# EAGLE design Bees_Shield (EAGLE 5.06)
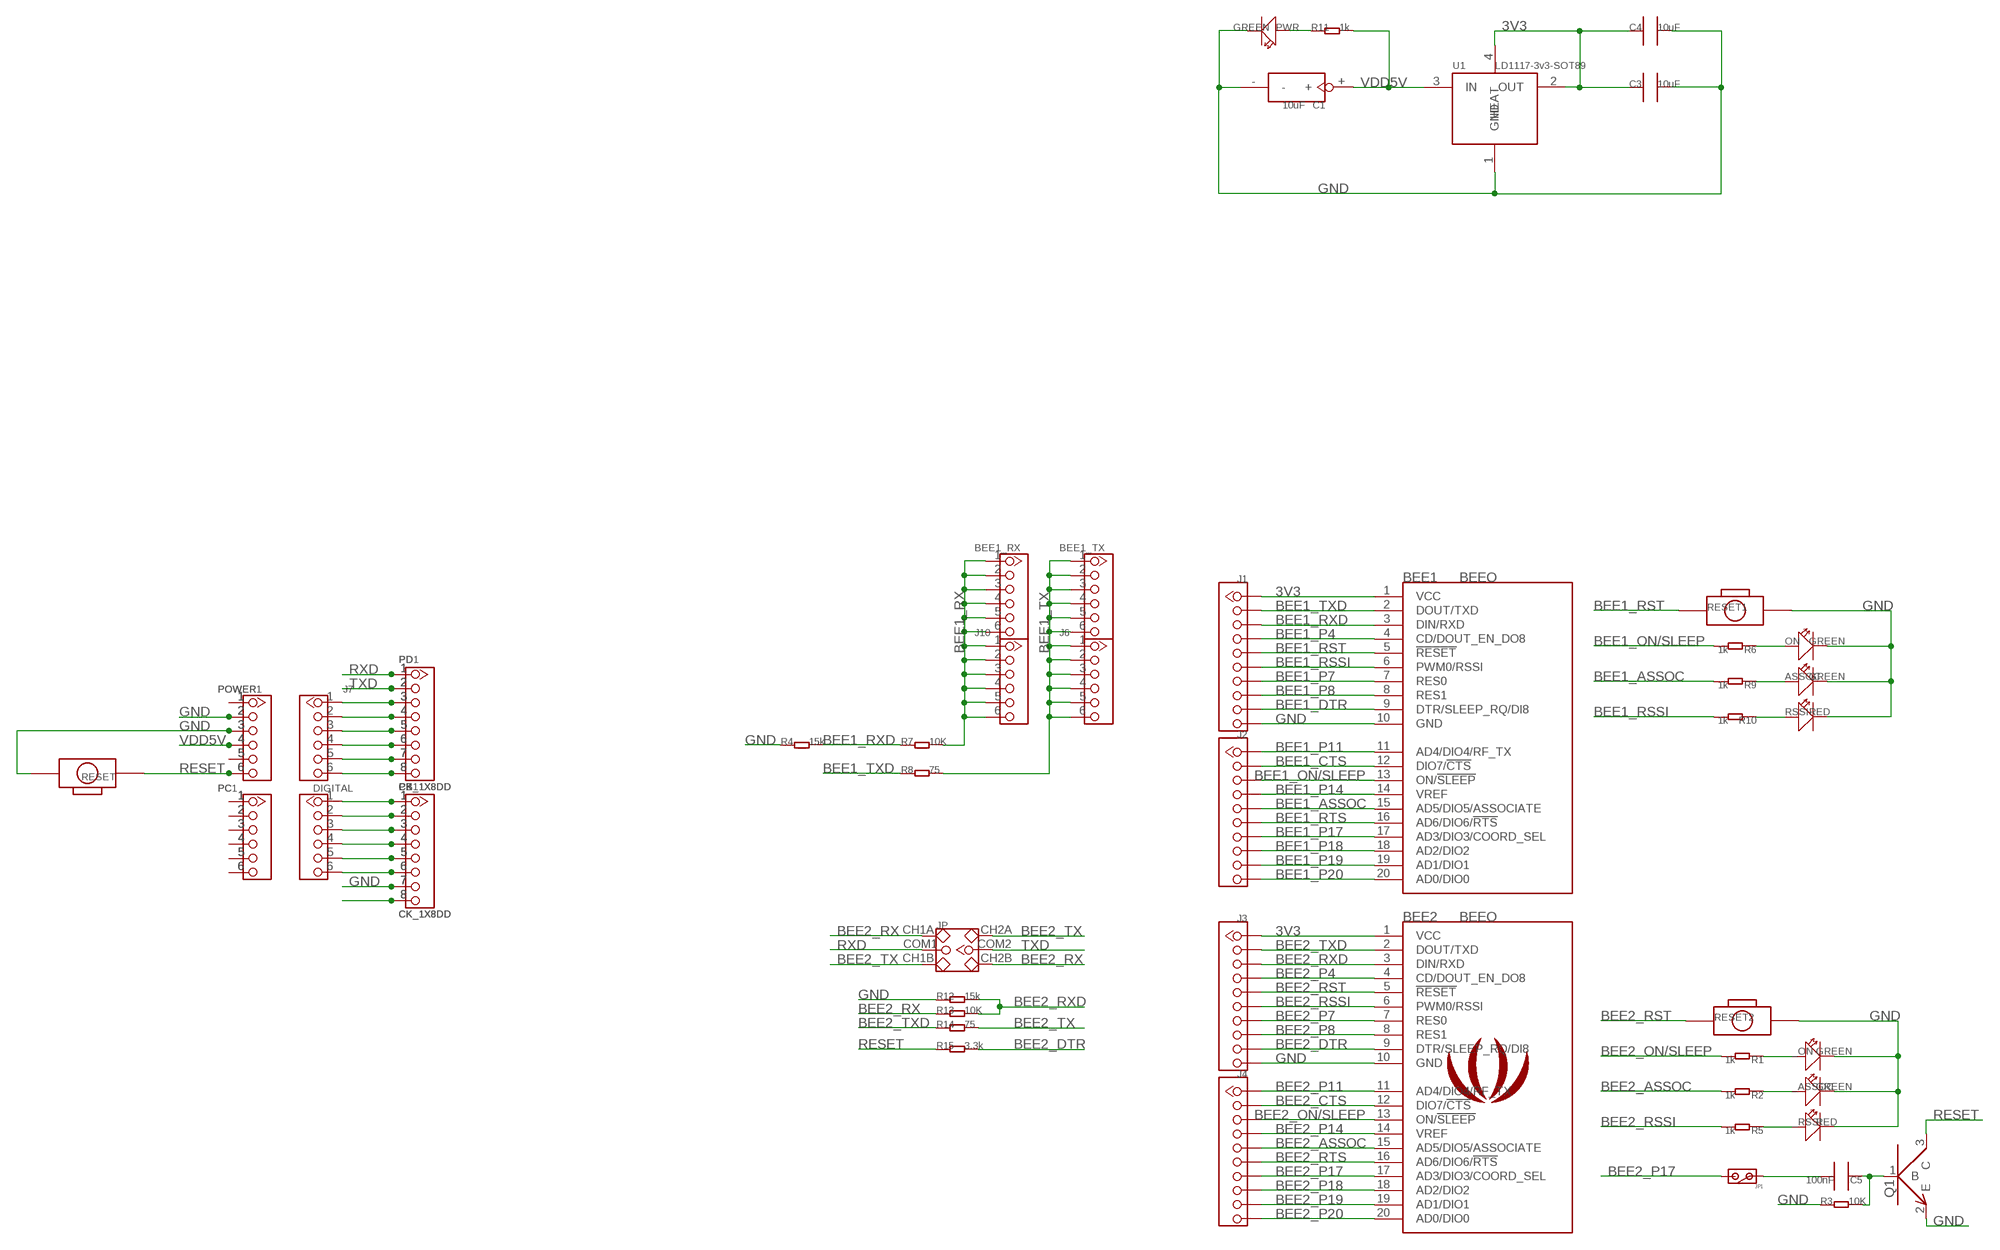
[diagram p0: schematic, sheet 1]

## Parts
_ASSOC  GREEN  LED0603_DD  [LED0603]
_ON  GREEN  LED0603_DD  [LED0603]
_RSSI  RED  LED0603_DD  [LED0603]
ASSOC  GREEN  LED0603_DD  [LED0603]
BEE1  BEEO  [BEE]
BEE1_RX  HEADER_1X6  [CK_1X6]
BEE1_TX  HEADER_1X6  [CK_1X6]
BEE2  BEEO  [BEE]
C1  10uF  C_TAN_B  [C_TAN_3X3.5]
C3  10uF  C0805  [0805]
C4  10uF  C0805  [0805]
C5  100nF  C0603  [0603]
DIGITAL  HEADER_1X6  [CK_1X6]
J1  CK1X10DD  [CK1X10]
J2  CK1X10DD  [CK1X10]
J3  CK1X10DD  [CK1X10]
J4  CK1X10DD  [CK1X10]
J6  HEADER_1X6  [CK_1X6]
J7  HEADER_1X6  [CK_1X6]
J10  HEADER_1X6  [CK_1X6]
JP  2.54SW_2CH_SMD  [7X7_SMD_2CH]
JP1  JP_SW  [JP_SW]
ON  GREEN  LED0603_DD  [LED0603]
PB  CK_1X8DD  [CK_1X8]
PB1  CK_1X8DD  [CK_1X8]
PC  HEADER_1X6  [CK_1X6]
PC1  HEADER_1X6  [CK_1X6]
PD  CK_1X8DD  [CK_1X8]
PD1  CK_1X8DD  [CK_1X8]
POWER  HEADER_1X6  [CK_1X6]
POWER1  HEADER_1X6  [CK_1X6]
PWR  GREEN  LED0603_DD  [LED0603]
Q1  NPN_9013  [SOT23]
R1  1k  R0603  [0603]
R2  1k  R0603  [0603]
R3  10K  R0603  [0603]
R4  15k  R0603  [0603]
R5  1k  R0603  [0603]
R6  1k  R0603  [0603]
R7  10K  R0603  [0603]
R8  75  R0603  [0603]
R9  1k  R0603  [0603]
R10  1k  R0603  [0603]
R11  1k  R0603  [0603]
R12  15k  R0603  [0603]
R13  10K  R0603  [0603]
R14  75  R0603  [0603]
R15  3.3k  R0603  [0603]
RESET  BOTTON_1  BOTTON_1_DP  [BTN_5.0_RST]
RESET1  BOTTON_1  BOTTON_1_DP  [BTN_5.0_RST]
RESET2  BOTTON_1  BOTTON_1_DP  [BTN_5.0_RST]
RSSI  RED  LED0603_DD  [LED0603]
U1  LD1117-3v3-SOT89  LD1117SOT89  [SOT89]
U$1  SEEEDSTUDIO  [SEEED_MASK]

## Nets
3V3: BEE1.1(VCC) BEE2.1(VCC) C3.1 C4.1 J1.1 J3.1 U1.2(OUT) U1.4(HEAT)
BEE1_ASSOC: BEE1.15(AD5/DIO5/ASSOCIATE) J2.5 R9.2
BEE1_CTS: BEE1.12(DIO7/!CTS) J2.2
BEE1_DTR: BEE1.9(DTR/SLEEP_RQ/DI8) J1.9
BEE1_ON/SLEEP: BEE1.13(ON/!SLEEP) J2.3 R6.2
BEE1_P4: BEE1.4(CD/DOUT_EN_DO8) J1.4
BEE1_P7: BEE1.7(RES0) J1.7
BEE1_P8: BEE1.8(RES1) J1.8
BEE1_P11: BEE1.11(AD4/DIO4/RF_TX) J2.1
BEE1_P14: BEE1.14(VREF) J2.4
BEE1_P17: BEE1.17(AD3/DIO3/COORD_SEL) J2.7
BEE1_P18: BEE1.18(AD2/DIO2) J2.8
BEE1_P19: BEE1.19(AD1/DIO1) J2.9
BEE1_P20: BEE1.20(AD0/DIO0) J2.10
BEE1_RSSI: BEE1.6(PWM0/RSSI) J1.6 R10.2
BEE1_RST: BEE1.5(!RESET) J1.5 RESET1.P$1
BEE1_RTS: BEE1.16(AD6/DIO6/!RTS) J2.6
BEE1_RX: BEE1_RX.1 BEE1_RX.2 BEE1_RX.3 BEE1_RX.4 BEE1_RX.5 BEE1_RX.6 J10.1 J10.2 J10.3 J10.4 J10.5 J10.6 R7.2
BEE1_RXD: BEE1.3(DIN/RXD) J1.3 R4.2 R7.1
BEE1_TX: BEE1_TX.1 BEE1_TX.2 BEE1_TX.3 BEE1_TX.4 BEE1_TX.5 BEE1_TX.6 J6.1 J6.2 J6.3 J6.4 J6.5 J6.6 R8.2
BEE1_TXD: BEE1.2(DOUT/TXD) J1.2 R8.1
BEE2_ASSOC: BEE2.15(AD5/DIO5/ASSOCIATE) J4.5 R2.2
BEE2_CTS: BEE2.12(DIO7/!CTS) J4.2
BEE2_DTR: BEE2.9(DTR/SLEEP_RQ/DI8) J3.9 R15.2
BEE2_ON/SLEEP: BEE2.13(ON/!SLEEP) J4.3 R1.2
BEE2_P4: BEE2.4(CD/DOUT_EN_DO8) J3.4
BEE2_P7: BEE2.7(RES0) J3.7
BEE2_P8: BEE2.8(RES1) J3.8
BEE2_P11: BEE2.11(AD4/DIO4/RF_TX) J4.1
BEE2_P14: BEE2.14(VREF) J4.4
BEE2_P17: BEE2.17(AD3/DIO3/COORD_SEL) J4.7 JP1.2
BEE2_P18: BEE2.18(AD2/DIO2) J4.8
BEE2_P19: BEE2.19(AD1/DIO1) J4.9
BEE2_P20: BEE2.20(AD0/DIO0) J4.10
BEE2_RSSI: BEE2.6(PWM0/RSSI) J3.6 R5.2
BEE2_RST: BEE2.5(!RESET) J3.5 RESET2.P$1
BEE2_RTS: BEE2.16(AD6/DIO6/!RTS) J4.6
BEE2_RX: JP.CH1A JP.CH2B R13.1
BEE2_RXD: BEE2.3(DIN/RXD) J3.3 R12.2 R13.2
BEE2_TX: JP.CH1B JP.CH2A R14.2
BEE2_TXD: BEE2.2(DOUT/TXD) J3.2 R14.1
GND: _ASSOC.2(-) _ON.2(-) _RSSI.2(-) ASSOC.2(-) BEE1.10(GND) BEE2.10(GND) C1.- C3.2 C4.2 J1.10 J3.10 ON.2(-) PB1.7 PB.7 POWER1.2 POWER1.3 POWER.2 POWER.3 PWR.2(-) Q1.2(E) R3.1 R4.1 R12.1 RESET1.P$2 RESET2.P$2 RESET.P$2 RSSI.2(-) U1.1(GND)
N$1: C5.1 Q1.1(B) R3.2
N$2: C5.2 JP1.1
N$3: _ON.1(+) R1.1
N$4: _ASSOC.1(+) R2.1
N$5: _RSSI.1(+) R5.1
N$6: PWR.1(+) R11.1
N$7: ON.1(+) R6.1
N$8: ASSOC.1(+) R9.1
N$9: J7.1 PD1.3 PD.3
N$10: J7.2 PD1.4 PD.4
N$11: R10.1 RSSI.1(+)
N$12: J7.3 PD1.5 PD.5
N$13: J7.4 PD1.6 PD.6
N$14: J7.5 PD1.7 PD.7
N$15: J7.6 PD1.8 PD.8
N$17: DIGITAL.2 PB1.2 PB.2
N$18: DIGITAL.3 PB1.3 PB.3
N$19: DIGITAL.4 PB1.4 PB.4
N$20: DIGITAL.5 PB1.5 PB.5
N$21: DIGITAL.6 PB1.6 PB.6
N$23: PB1.8 PB.8
N$24: DIGITAL.1 PB1.1 PB.1
N$48: PC1.1 PC.1
N$49: PC1.2 PC.2
N$140: PC1.3 PC.3
N$218: PC1.4 PC.4
N$228: PC1.5 PC.5
N$233: PC1.6 PC.6
N$234: POWER1.1 POWER.1
N$236: POWER1.5 POWER.5
RESET: POWER1.6 POWER.6 Q1.3(C) R15.1 RESET.P$1
RXD: JP.COM1 PD1.1 PD.1
TXD: JP.COM2 PD1.2 PD.2
VDD5V: C1.+ POWER1.4 POWER.4 R11.2 U1.3(IN)

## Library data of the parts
_ASSOC _ON _RSSI ASSOC ON PWR RSSI = CPT_SMD:LED0603
BEE1 BEE2 = EXT_moudle:BEE
BEE1_RX BEE1_TX DIGITAL J6 J7 J10 PC PC1 POWER POWER1 = CONNECTER:HEADER_1X6
C1 = CPT_SMD:C_TAN
C3 C4 = CPT_SMD:C0805
C5 = CPT_SMD:C0603; C0603: 100N
J1-J4 = CONNECTER:CK1X10
JP = CPT_CJ:2.54SW_2CH
JP1 = CPT_SMD:JP_SW
PB PB1 PD PD1 = CONNECTER:CK_1X8
Q1 = CPT_SMD:NPN_9013
R1-R15 = CPT_SMD:R0603
RESET RESET1 RESET2 = CPT_SMD:BOTTON_1
U1 = ICs_v54:LD1117
U$1 = logo:SEEEDSTUDIO

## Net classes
1 power: width 0.61 mm

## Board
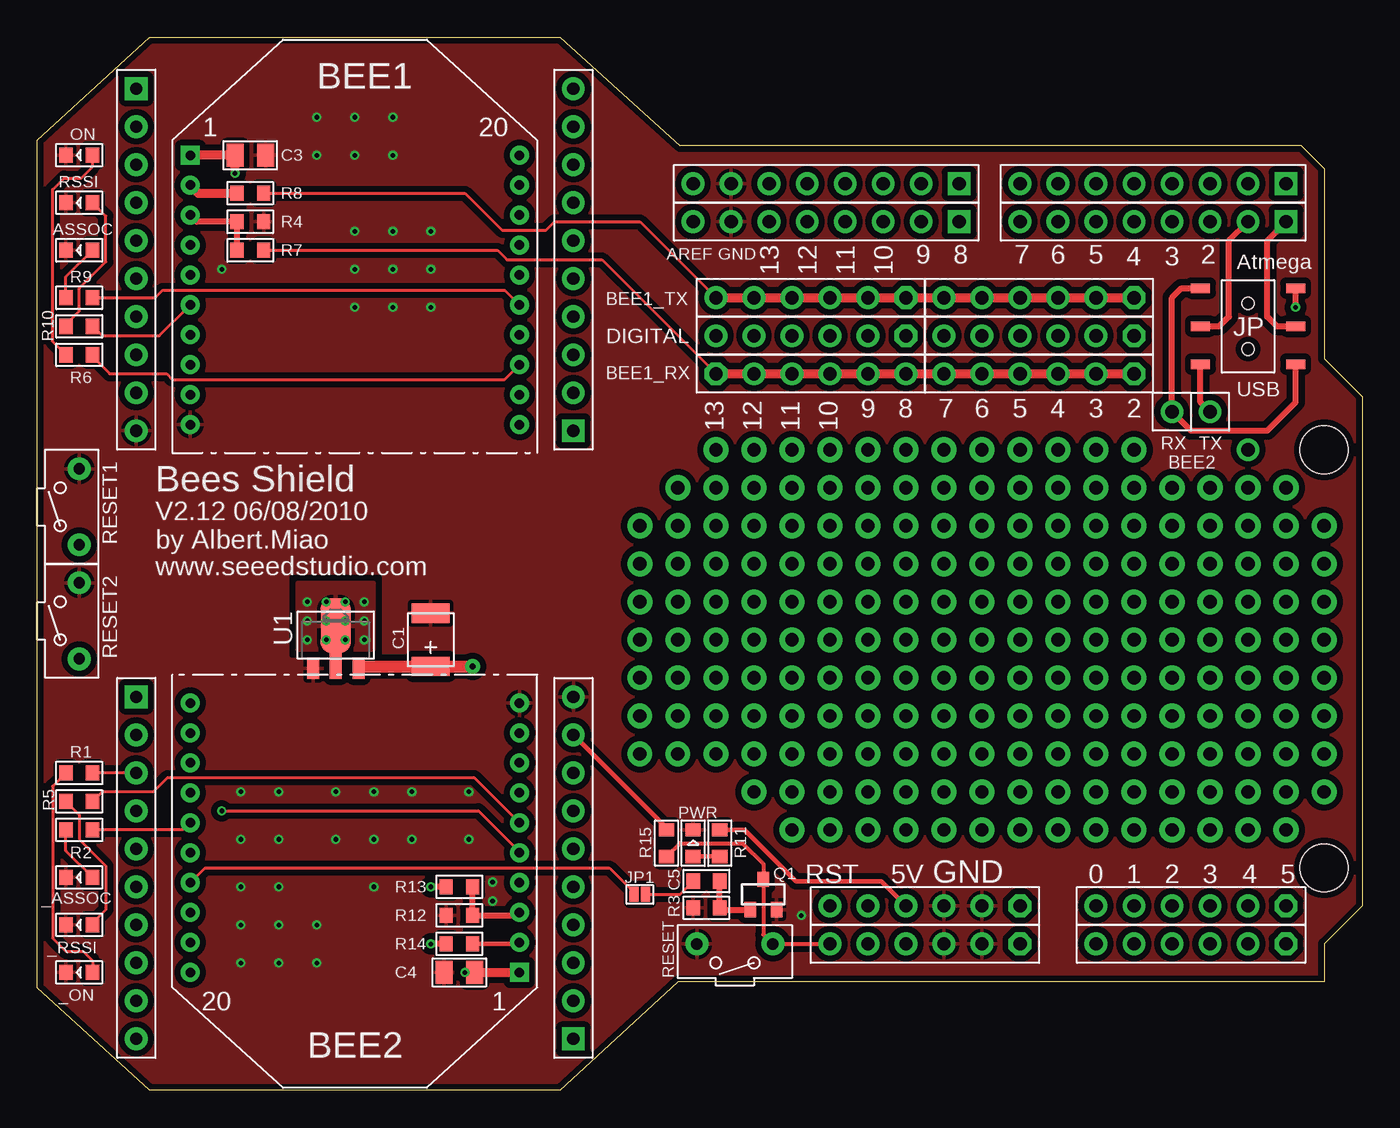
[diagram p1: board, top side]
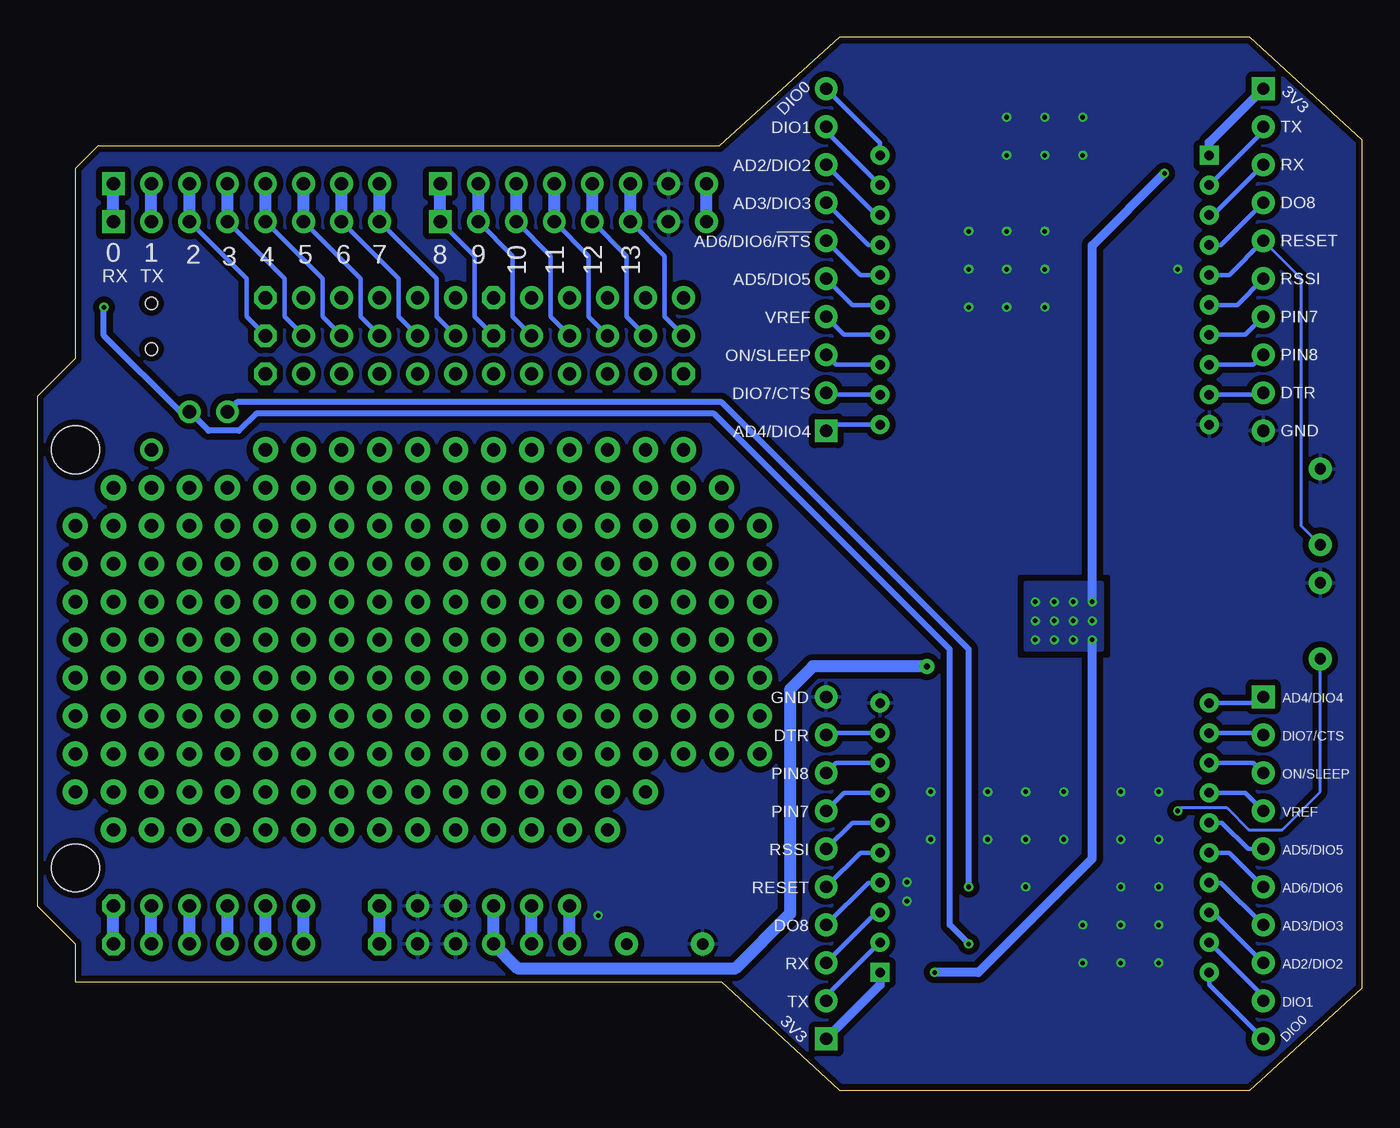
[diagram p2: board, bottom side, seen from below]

Size 88.52 x 70.36 mm. Coordinates in mm from the lower left corner, seen from the top.
Outline: 0,6.86 0,63.5 7.49,70.36 34.92,70.36 42.93,63.12 84.46,63.12 85.98,61.59 85.98,48.9 88.52,46.35 88.52,12.32 85.98,9.78 85.98,7.24 42.8,7.24 34.92,0 7.49,0 0,6.86
Copper layers (1*16): Top 0.035mm / dielectric 1.5mm / Bottom 0.035mm
Design rules "rule_manufacture *": minimum track width 8mil, minimum drill 12mil, track to track 8mil, track to pad 8mil, pad to pad 6mil, via to via 10mil, smd to smd 0mil, copper to edge 10mil, drill to drill 10mil, minimum pad ring 10mil, minimum via ring 6mil, stop-mask expansion 2mil, vias tented up to drill 25mil, thermal gap 10mil
Holes 3.2 mm at 85.98,42.8 85.98,14.86

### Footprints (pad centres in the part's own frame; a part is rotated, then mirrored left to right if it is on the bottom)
LED0603 = smd 0.889 x 1.016: 1 -0.889,0; 2 0.889,0
BEE = drill 0.635 pad 1.27 square: 1 -11,0 | drill 0.635 pad 1.27 round: 2 -11,-2; 3 -11,-4; 4 -11,-6; 5 -11,-8; 6 -11,-10; 7 -11,-12; 8 -11,-14; 9 -11,-16; 10 -11,-18; 11 11,-18; 12 11,-16; 13 11,-14; 14 11,-12; 15 11,-10; 16 11,-8; 17 11,-6; 18 11,-4; 19 11,-2; 20 11,0
CK_1X6 = drill 0.889 pad 1.524 octagon: 1 0,6.35 | drill 0.889 pad 1.524 round: 2 0,3.81; 3 0,1.27; 4 0,-1.27; 5 0,-3.81; 6 0,-6.35
C_TAN_3X3.5 = smd 2.54 x 1.27: + 0,1.778; - 0,-1.778
0805 = smd 1.143 x 1.524: 1 -1.016,0; 2 1.016,0
0603 = smd 0.889 x 1.016: 1 -0.889,0; 2 0.889,0
CK1X10 = drill 0.813 pad 1.524 square: 1 0,11.43 | drill 0.813 pad 1.524 round: 2 0,8.89; 3 0,6.35; 4 0,3.81; 5 0,1.27; 6 0,-1.27; 7 0,-3.81; 8 0,-6.35; 9 0,-8.89; 10 0,-11.43
7X7_SMD_2CH = smd 1.27 x 0.635: CH1A -3.175,2.54; CH1B -3.175,-2.54; CH2A 3.175,2.54; CH2B 3.175,-2.54; COM1 -3.175,0; COM2 3.175,0 | hole 0.813: 0,1.524; 0,-1.524
JP_SW = smd 1.016 x 0.61: 1 0,0.381; 2 0,-0.381
CK_1X8 = drill 0.889 pad 1.524 square: 1 0,8.89 | drill 0.889 pad 1.524 round: 2 0,6.35; 3 0,3.81; 4 0,1.27; 5 0,-1.27; 6 0,-3.81; 7 0,-6.35; 8 0,-8.89
SOT23 = smd 0.762 x 1.016: 1 -0.889,-1.016; 2 0.889,-1.016; 3 0,1.016
BTN_5.0_RST = drill 0.762 pad 1.524 round: P$1 0,2.54; P$2 0,-2.54
SOT89 = smd 0.8 x 1.4: 1 -1.524,-1.905; 3 1.524,-1.905 | smd 0.8 x 1.9: 2 0,-1.651 | smd 2.032 x 3.65: 4 0,0.94

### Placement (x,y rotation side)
_ASSOC  2.79,14.22 180 top
_ON  2.79,7.87 180 top
_RSSI  2.79,11.05 180 top
ASSOC  2.79,56.13 180 top
BEE1  21.21,62.48 0 top
BEE1_RX  51.69,47.88 90 top
BEE1_TX  51.69,52.96 270 top
BEE2  21.21,7.87 180 top
C1  26.29,30.1 180 top
C3  14.22,62.48 0 top
C4  28.19,7.87 180 top
C5  44.7,13.97 180 top
DIGITAL  51.69,50.42 270 top
J1  6.6,55.5 0 top
J2  35.81,55.5 180 top
J3  35.81,14.86 180 top
J4  6.6,14.86 0 top
J6  66.93,52.96 270 top
J7  66.93,50.42 270 top
J10  66.93,47.88 270 top
JP  80.9,51.05 180 top
JP1  40.26,13.08 270 top
ON  2.79,62.48 180 top
PB  52.7,58.04 270 top
PB1  52.7,60.58 270 top
PC  77.09,9.78 270 top
PC1  77.09,12.32 270 top
PD  74.55,58.04 270 top
PD1  74.55,60.58 270 top
POWER  59.31,9.78 270 top
POWER1  59.31,12.32 270 top
PWR  43.81,16.51 90 top
Q1  48.51,13.08 0 top
R1  2.79,21.21 0 top
R2  2.79,17.4 0 top
R3  44.7,12.19 0 top
R4  14.22,58.04 180 top
R5  2.79,19.3 0 top
R6  2.79,49.15 0 top
R7  14.22,56.13 0 top
R8  14.22,59.94 0 top
R9  2.79,52.96 0 top
R10  2.79,51.05 0 top
R11  45.59,16.51 90 top
R12  28.19,11.68 0 top
R13  28.19,13.59 0 top
R14  28.19,9.78 180 top
R15  42.04,16.51 90 top
RESET  46.61,9.78 270 top
RESET1  2.79,38.99 180 top
RESET2  2.79,31.37 180 top
RSSI  2.79,59.31 180 top
U1  19.94,30.1 0 top
U$1  29.46,38.35 0 top

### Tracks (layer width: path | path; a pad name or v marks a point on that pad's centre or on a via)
3V3  (via drill 0.3 pad 0.61)
  Top 0.61: U1.2 U1.4 | U1.4 | v13.21,61.28 C3.1 BEE1.1 | v28.57,7.87 C4.1 BEE2.1
  Bottom 0.61: BEE1.1 10.21,63.32 J1.1 | BEE2.1 32.21,7.03 J3.1 | v18.03,32.64 18.03,56.45 v13.21,61.28 | v18.03,30.1 18.03,15.49 25.65,7.87 v28.57,7.87
  other vias: 19.3,32.64 20.57,32.64 21.84,32.64 21.84,31.37 21.84,30.1 20.57,31.37 18.03,31.37 19.3,31.37 19.3,30.1 20.57,30.1
  pour Top: 17.4,33.91 22.48,33.91 22.48,29.46 17.4,29.46
  pour Bottom: 17.4,33.91 22.48,33.91 22.48,29.46 17.4,29.46
BEE1_ASSOC
  Top 0.203: BEE1.15 31.23,53.47 8.38,53.47 7.87,52.96 R9.2
  Bottom 0.305: BEE1.15 34.07,52.48 J2.5
BEE1_CTS
  Bottom 0.305: BEE1.12 35.69,46.48 J2.2
BEE1_DTR
  Bottom 0.305: BEE1.9 6.73,46.48 J1.9
BEE1_ON/SLEEP
  Top 0.203: BEE1.13 31.22,47.5 9.02,47.5 8.64,47.88 4.83,47.88 3.68,49.02 R6.2
  Bottom 0.305: BEE1.13 35.15,48.48 J2.3
BEE1_P4
  Bottom 0.305: BEE1.4 9.43,56.48 J1.4
BEE1_P7
  Bottom 0.305: BEE1.7 7.81,50.48 J1.7
BEE1_P8
  Bottom 0.305: BEE1.8 7.27,48.48 J1.8
BEE1_P11
  Bottom 0.305: BEE1.11 35.4,44.48 J2.1
BEE1_P14
  Bottom 0.305: BEE1.14 34.61,50.48 J2.4
BEE1_P17
  Bottom 0.305: BEE1.17 32.99,56.48 J2.7
BEE1_P18
  Bottom 0.305: BEE1.18 32.45,58.48 J2.8
BEE1_P19
  Bottom 0.305: BEE1.19 35.81,64.09 J2.9
BEE1_P20
  Bottom 0.305: BEE1.20 32.21,63.32 J2.10
BEE1_RSSI
  Top 0.203: R10.2 4.32,50.42 8.14,50.42 BEE1.6
  Bottom 0.305: BEE1.6 8.35,52.48 J1.6
BEE1_RST
  Bottom 0.203: RESET1.P$1 4.06,37.72 4.06,54.23 J1.5
  Bottom 0.305: J1.5 8.89,54.48 BEE1.5
BEE1_RTS
  Bottom 0.305: BEE1.16 33.53,54.48 J2.6
BEE1_RX
  Top 0.203: BEE1_RX.1 37.72,55.5 31.37,55.5 30.73,56.13 R7.2
  Top 0.61: BEE1_RX.1 BEE1_RX.2 BEE1_RX.3 BEE1_RX.4 BEE1_RX.5 BEE1_RX.6 J10.6 J10.5 J10.4 J10.3 J10.2 J10.1
BEE1_RXD
  Top 0.406: R7.1 R4.2 10.65,58.04 BEE1.3
  Bottom 0.305: BEE1.3 9.97,58.48 J1.3
BEE1_TX
  Top 0.203: R8.2 28.57,59.94 31.05,57.47 33.97,57.47 34.54,58.04 40.26,58.04 BEE1_TX.6
  Top 0.61: J6.1 J6.2 J6.3 J6.4 J6.5 J6.6 BEE1_TX.1 BEE1_TX.2 BEE1_TX.3 BEE1_TX.4 BEE1_TX.5 BEE1_TX.6
BEE1_TXD
  Top 0.61: R8.1 10.75,59.94 BEE1.2
  Bottom 0.305: BEE1.2 6.6,64.09 J1.2
BEE2_ASSOC
  Top 0.203: R2.2 9.73,17.4 BEE2.15
  Bottom 0.305: BEE2.15 9.37,17.87 7.62,16.13 J4.5
BEE2_CTS
  Bottom 0.305: BEE2.12 6.73,23.87 J4.2
BEE2_DTR
  Top 0.305: R15.2 42.04,17.53 J3.9
  Bottom 0.305: BEE2.9 35.69,23.87 J3.9
BEE2_ON/SLEEP
  Top 0.203: J4.3 R1.2
  Bottom 0.305: BEE2.13 7.27,21.87 J4.3
BEE2_P4
  Bottom 0.305: BEE2.4 32.99,13.87 J3.4
BEE2_P7
  Bottom 0.305: BEE2.7 34.61,19.87 J3.7
BEE2_P8
  Bottom 0.305: BEE2.8 35.15,21.87 J3.8
BEE2_P11
  Bottom 0.305: BEE2.11 7.02,25.87 J4.1
BEE2_P14
  Bottom 0.305: BEE2.14 7.81,19.87 J4.4
BEE2_P17
  Top 0.203: BEE2.17 11.19,14.86 38.23,14.86 39.88,13.21 JP1.2
  Bottom 0.305: BEE2.17 9.43,13.87 J4.7
BEE2_P18
  Bottom 0.305: BEE2.18 9.97,11.87 J4.8
BEE2_P19
  Bottom 0.305: J4.9 6.6,6.27 BEE2.19
BEE2_P20
  Bottom 0.305: BEE2.20 10.21,7.03 J4.10
BEE2_RSSI
  Top 0.203: BEE2.6 29.19,20.89 8.7,20.89 7.75,19.94 4.32,19.94 R5.2
  Bottom 0.305: BEE2.6 34.07,17.87 J3.6
BEE2_RST  (via drill 0.3 pad 0.61)
  Top 0.203: v12.32,18.67 29.46,18.67 32,16.13 32,16.08 BEE2.5
  Bottom 0.203: RESET2.P$1 2.79,19.94 5.33,17.4 7.56,17.4 9.02,18.86 12.13,18.86 v12.32,18.67
  Bottom 0.305: BEE2.5 33.53,15.87 J3.5
BEE2_RTS
  Bottom 0.305: BEE2.16 8.89,15.87 J4.6
BEE2_RX  (via drill 0.3 pad 0.61, 0.89 pad 1.52)
  Top 0.406: JP.CH2B 76.45,53.59 75.82,52.96 v75.82,45.34 77.09,44.07 82.17,44.07 84.07,45.97 JP.CH1A | R13.1 v26.29,13.59
  Bottom 0.406: v26.29,13.59 26.29,29.46 42.8,45.97 75.18,45.97 v75.82,45.34
BEE2_RXD
  Top 0.406: R13.2 R12.2 32.02,11.68 BEE2.3
  Bottom 0.305: BEE2.3 32.45,11.87 J3.3
BEE2_TX  (via drill 0.3 pad 0.61, 0.89 pad 1.52)
  Top 0.406: v84.07,52.32 JP.CH1B | R14.2 v26.29,9.78 | JP.CH2A 77.72,45.97 v78.36,45.34
  Bottom 0.406: v84.07,52.32 84.07,50.42 78.99,45.34 v78.36,45.34 77.09,44.07 75.06,44.07 73.91,45.21 43.31,45.21 27.56,29.46 27.56,11.05 v26.29,9.78
BEE2_TXD
  Top 0.305: R14.1 32.11,9.78 BEE2.2
  Bottom 0.305: J3.2 35.81,6.27 BEE2.2
GND  (via drill 0.3 pad 0.61)
  other vias: 30.42,13.91 30.42,12.64 28.83,16.76 28.83,19.94 25.02,16.76 25.02,19.94 22.48,19.94 22.48,16.76 19.94,19.94 19.94,16.76 16.13,16.76 16.13,19.94 13.59,19.94 13.59,16.76 22.48,13.59 16.13,13.59 13.59,13.59 16.13,11.05 13.59,11.05 13.59,8.51 16.13,8.51 18.67,11.05 18.67,8.51 21.21,62.48 21.21,65.02 23.75,62.48 23.75,65.02 18.67,65.02 18.67,62.48 21.21,54.86 23.75,54.86 26.29,54.86 12.32,54.86 51.05,11.68 21.21,57.4 23.75,57.4 26.29,57.4 21.21,52.32 23.75,52.32 26.29,52.32
  pour Bottom (isolate 0.406, rank 6): 0,63.5 7.49,70.36 34.92,70.36 43.05,63.12 84.58,63.12 85.98,61.72 85.98,48.9 88.52,46.35 88.52,12.32 85.98,9.78 85.98,7.24 42.93,7.24 34.92,0 7.49,0 0,6.86
  pour Top (isolate 0.406, rank 6): 0,63.5 7.49,70.36 34.92,70.36 43.05,63.12 84.58,63.12 85.98,61.72 85.98,48.9 88.52,46.35 88.52,12.32 85.98,9.78 85.98,7.24 42.93,7.24 34.92,0 7.49,0 0,6.86
N$1
  Top 0.406: Q1.1 45.72,12.07 R3.2 C5.1
N$2
  Top 0.203: JP1.1 42.93,13.08 C5.2
N$3
  Top 0.203: _ON.1 3.68,8.64 3.05,9.27 1.91,9.27 1.02,10.16 1.02,20.32 R1.1
N$4
  Top 0.203: R2.1 1.91,16 _ASSOC.1
N$5
  Top 0.203: _RSSI.1 3.68,11.18 4.57,12.07 4.57,14.99 2.79,16.76 2.79,18.41 R5.1
N$6
  Top 0.305: PWR.1 R11.1
N$7
  Top 0.203: R6.1 1.02,50.04 1.02,60.2 1.78,60.96 2.92,60.96 3.68,61.72 ON.1
N$8
  Top 0.203: R9.1 1.91,54.36 ASSOC.1
N$9
  Bottom 0.305: PD.3 74.55,54.23 74.55,51.69 J7.1
  Bottom 0.813: PD.3 PD1.3
N$10
  Bottom 0.305: PD.4 72.01,54.23 72.01,51.69 J7.2
  Bottom 0.813: PD.4 PD1.4
N$11
  Top 0.203: R10.1 1.91,51.18 2.79,52.07 2.79,53.59 4.57,55.37 4.57,58.42 RSSI.1
N$12
  Bottom 0.305: PD.5 69.47,54.23 69.47,51.69 J7.3
  Bottom 0.813: PD.5 PD1.5
N$13
  Bottom 0.305: PD.6 66.93,54.23 66.93,51.69 J7.4
  Bottom 0.813: PD.6 PD1.6
N$14
  Bottom 0.305: PD.7 64.39,54.23 64.39,51.69 J7.5
  Bottom 0.813: PD.7 PD1.7
N$15
  Bottom 0.305: PD.8 61.85,54.23 61.85,51.69 J7.6
  Bottom 0.813: PD.8 PD1.8
N$16  (via drill 0.89 pad 1.52)
  other vias: 80.9,42.8
N$17
  Bottom 0.305: PB.2 56.77,55.75 56.77,51.69 DIGITAL.2
  Bottom 0.813: PB.2 PB1.2
N$18
  Bottom 0.305: PB.3 54.23,55.75 54.23,51.69 DIGITAL.3
  Bottom 0.813: PB.3 PB1.3
N$19
  Bottom 0.305: PB.4 51.69,55.75 51.69,51.69 DIGITAL.4
  Bottom 0.813: PB.4 PB1.4
N$20
  Bottom 0.305: PB.5 49.15,55.75 49.15,51.69 DIGITAL.5
  Bottom 0.813: PB.5 PB1.5
N$21
  Bottom 0.305: PB.6 46.61,55.75 46.61,51.69 DIGITAL.6
  Bottom 0.813: PB.6 PB1.6
N$22  (via drill 0.89 pad 1.68)
  other vias: 80.9,40.26
N$23
  Bottom 0.813: PB.8 PB1.8
N$24
  Bottom 0.305: PB.1 59.31,55.75 59.31,51.69 DIGITAL.1
  Bottom 0.813: PB.1 PB1.1
N$25  (via drill 0.89 pad 1.68)
  other vias: 80.9,37.72
N$26  (via drill 0.89 pad 1.68)
  other vias: 80.9,35.18
N$27  (via drill 0.89 pad 1.68)
  other vias: 80.9,32.64
N$28  (via drill 0.89 pad 1.68)
  other vias: 80.9,30.1
N$29  (via drill 0.89 pad 1.68)
  other vias: 80.9,27.56
N$30  (via drill 0.89 pad 1.68)
  other vias: 80.9,25.02
N$31  (via drill 0.89 pad 1.68)
  other vias: 80.9,22.48
N$32  (via drill 0.89 pad 1.68)
  other vias: 80.9,19.94
N$33  (via drill 0.89 pad 1.68)
  other vias: 80.9,17.4
N$38  (via drill 0.89 pad 1.68)
  other vias: 78.36,17.4
N$39  (via drill 0.89 pad 1.68)
  other vias: 78.36,19.94
N$40  (via drill 0.89 pad 1.68)
  other vias: 78.36,22.48
N$41  (via drill 0.89 pad 1.68)
  other vias: 78.36,25.02
N$42  (via drill 0.89 pad 1.68)
  other vias: 78.36,27.56
N$43  (via drill 0.89 pad 1.68)
  other vias: 78.36,30.1
N$44  (via drill 0.89 pad 1.68)
  other vias: 78.36,32.64
N$45  (via drill 0.89 pad 1.68)
  other vias: 78.36,35.18
N$46  (via drill 0.89 pad 1.68)
  other vias: 78.36,37.72
N$47  (via drill 0.89 pad 1.68)
  other vias: 78.36,40.26
N$48
  Bottom 0.813: PC.1 PC1.1
N$49
  Bottom 0.813: PC.2 PC1.2
N$50  (via drill 0.89 pad 1.68)
  other vias: 75.82,40.26
N$51  (via drill 0.89 pad 1.68)
  other vias: 75.82,37.72
N$52  (via drill 0.89 pad 1.68)
  other vias: 75.82,35.18
N$53  (via drill 0.89 pad 1.68)
  other vias: 75.82,32.64
N$54  (via drill 0.89 pad 1.68)
  other vias: 75.82,30.1
N$55  (via drill 0.89 pad 1.68)
  other vias: 75.82,27.56
N$56  (via drill 0.89 pad 1.68)
  other vias: 75.82,25.02
N$57  (via drill 0.89 pad 1.68)
  other vias: 75.82,22.48
N$58  (via drill 0.89 pad 1.68)
  other vias: 75.82,19.94
N$59  (via drill 0.89 pad 1.68)
  other vias: 75.82,17.4
N$61  (via drill 0.89 pad 1.65)
  other vias: 52.96,17.4
N$62  (via drill 0.89 pad 1.68)
  other vias: 83.44,17.4
N$63  (via drill 0.89 pad 1.65)
  other vias: 50.42,17.4
N$64  (via drill 0.89 pad 1.68)
  other vias: 83.44,19.94
N$65  (via drill 0.89 pad 1.68)
  other vias: 83.44,22.48
N$66  (via drill 0.89 pad 1.68)
  other vias: 83.44,25.02
N$67  (via drill 0.89 pad 1.68)
  other vias: 83.44,27.56
N$68  (via drill 0.89 pad 1.68)
  other vias: 83.44,30.1
N$69  (via drill 0.89 pad 1.68)
  other vias: 85.98,30.1
N$70  (via drill 0.89 pad 1.68)
  other vias: 85.98,27.56
N$71  (via drill 0.89 pad 1.68)
  other vias: 85.98,25.02
N$72  (via drill 0.89 pad 1.68)
  other vias: 85.98,22.48
N$73  (via drill 0.89 pad 1.68)
  other vias: 85.98,19.94
N$74  (via drill 0.89 pad 1.68)
  other vias: 83.44,40.26
N$75  (via drill 0.89 pad 1.68)
  other vias: 73.28,42.8
N$76  (via drill 0.89 pad 1.68)
  other vias: 73.28,40.26
N$77  (via drill 0.89 pad 1.68)
  other vias: 73.28,37.72
N$78  (via drill 0.89 pad 1.68)
  other vias: 73.28,35.18
N$79  (via drill 0.89 pad 1.68)
  other vias: 73.28,32.64
N$80  (via drill 0.89 pad 1.68)
  other vias: 73.28,30.1
N$81  (via drill 0.89 pad 1.68)
  other vias: 73.28,27.56
N$82  (via drill 0.89 pad 1.68)
  other vias: 73.28,25.02
N$83  (via drill 0.89 pad 1.68)
  other vias: 73.28,22.48
N$84  (via drill 0.89 pad 1.68)
  other vias: 73.28,19.94
N$85  (via drill 0.89 pad 1.68)
  other vias: 73.28,17.4
N$87  (via drill 0.89 pad 1.65)
  other vias: 50.42,19.94
N$88  (via drill 0.89 pad 1.65)
  other vias: 47.88,19.94
N$90  (via drill 0.89 pad 1.68)
  other vias: 70.74,17.4
N$91  (via drill 0.89 pad 1.68)
  other vias: 70.74,19.94
N$92  (via drill 0.89 pad 1.68)
  other vias: 70.74,22.48
N$93  (via drill 0.89 pad 1.68)
  other vias: 70.74,25.02
N$94  (via drill 0.89 pad 1.68)
  other vias: 70.74,27.56
N$95  (via drill 0.89 pad 1.68)
  other vias: 70.74,30.1
N$96  (via drill 0.89 pad 1.68)
  other vias: 70.74,32.64
N$97  (via drill 0.89 pad 1.68)
  other vias: 70.74,35.18
N$98  (via drill 0.89 pad 1.68)
  other vias: 70.74,37.72
N$99  (via drill 0.89 pad 1.68)
  other vias: 70.74,40.26
N$100  (via drill 0.89 pad 1.68)
  other vias: 70.74,42.8
N$101  (via drill 0.89 pad 1.68)
  other vias: 68.2,42.8
N$102  (via drill 0.89 pad 1.68)
  other vias: 68.2,40.26
N$103  (via drill 0.89 pad 1.68)
  other vias: 68.2,37.72
N$104  (via drill 0.89 pad 1.68)
  other vias: 68.2,35.18
N$105  (via drill 0.89 pad 1.68)
  other vias: 68.2,32.64
N$106  (via drill 0.89 pad 1.68)
  other vias: 68.2,30.1
N$107  (via drill 0.89 pad 1.68)
  other vias: 68.2,27.56
N$108  (via drill 0.89 pad 1.68)
  other vias: 68.2,25.02
N$109  (via drill 0.89 pad 1.68)
  other vias: 68.2,22.48
N$110  (via drill 0.89 pad 1.68)
  other vias: 68.2,19.94
N$111  (via drill 0.89 pad 1.68)
  other vias: 68.2,17.4
N$113  (via drill 0.89 pad 1.65)
  other vias: 47.88,22.48
N$114  (via drill 0.89 pad 1.65)
  other vias: 45.34,25.02
N$116  (via drill 0.89 pad 1.68)
  other vias: 65.66,17.4
N$117  (via drill 0.89 pad 1.68)
  other vias: 65.66,19.94
N$118  (via drill 0.89 pad 1.68)
  other vias: 65.66,22.48
N$119  (via drill 0.89 pad 1.68)
  other vias: 65.66,25.02
N$120  (via drill 0.89 pad 1.68)
  other vias: 65.66,27.56
N$121  (via drill 0.89 pad 1.68)
  other vias: 65.66,30.1
N$122  (via drill 0.89 pad 1.68)
  other vias: 65.66,32.64
N$123  (via drill 0.89 pad 1.68)
  other vias: 65.66,35.18
N$124  (via drill 0.89 pad 1.68)
  other vias: 65.66,37.72
N$125  (via drill 0.89 pad 1.68)
  other vias: 65.66,40.26
N$126  (via drill 0.89 pad 1.68)
  other vias: 65.66,42.8
N$127  (via drill 0.89 pad 1.68)
  other vias: 63.12,42.8
N$128  (via drill 0.89 pad 1.68)
  other vias: 63.12,40.26
N$129  (via drill 0.89 pad 1.68)
  other vias: 63.12,37.72
N$130  (via drill 0.89 pad 1.68)
  other vias: 63.12,35.18
N$131  (via drill 0.89 pad 1.68)
  other vias: 63.12,32.64
N$132  (via drill 0.89 pad 1.68)
  other vias: 63.12,30.1
N$133  (via drill 0.89 pad 1.68)
  other vias: 63.12,25.02
N$134  (via drill 0.89 pad 1.68)
  other vias: 63.12,27.56
N$135  (via drill 0.89 pad 1.68)
  other vias: 63.12,22.48
N$136  (via drill 0.89 pad 1.68)
  other vias: 63.12,19.94
N$137  (via drill 0.89 pad 1.68)
  other vias: 63.12,17.4
N$139  (via drill 0.89 pad 1.65)
  other vias: 45.34,22.48
N$140
  Bottom 0.813: PC.3 PC1.3
N$142  (via drill 0.89 pad 1.68)
  other vias: 60.58,17.4
N$143  (via drill 0.89 pad 1.68)
  other vias: 60.58,19.94
N$144  (via drill 0.89 pad 1.68)
  other vias: 60.58,22.48
N$145  (via drill 0.89 pad 1.68)
  other vias: 60.58,25.02
N$146  (via drill 0.89 pad 1.68)
  other vias: 60.58,27.56
N$147  (via drill 0.89 pad 1.68)
  other vias: 60.58,30.1
N$148  (via drill 0.89 pad 1.68)
  other vias: 60.58,32.64
N$149  (via drill 0.89 pad 1.68)
  other vias: 60.58,35.18
N$150  (via drill 0.89 pad 1.68)
  other vias: 60.58,37.72
N$151  (via drill 0.89 pad 1.68)
  other vias: 60.58,40.26
N$152  (via drill 0.89 pad 1.68)
  other vias: 60.58,42.8
N$153  (via drill 0.89 pad 1.68)
  other vias: 58.04,42.8
N$154  (via drill 0.89 pad 1.68)
  other vias: 58.04,40.26
N$155  (via drill 0.89 pad 1.68)
  other vias: 58.04,37.72
N$156  (via drill 0.89 pad 1.68)
  other vias: 58.04,35.18
N$157  (via drill 0.89 pad 1.68)
  other vias: 58.04,32.64
N$158  (via drill 0.89 pad 1.68)
  other vias: 58.04,27.56
N$159  (via drill 0.89 pad 1.68)
  other vias: 58.04,30.1
N$160  (via drill 0.89 pad 1.68)
  other vias: 58.04,22.48
N$161  (via drill 0.89 pad 1.68)
  other vias: 58.04,25.02
N$162  (via drill 0.89 pad 1.68)
  other vias: 58.04,19.94
N$163  (via drill 0.89 pad 1.68)
  other vias: 58.04,17.4
N$165  (via drill 0.89 pad 1.68)
  other vias: 55.5,17.4
N$166  (via drill 0.89 pad 1.68)
  other vias: 55.5,19.94
N$167  (via drill 0.89 pad 1.68)
  other vias: 55.5,22.48
N$168  (via drill 0.89 pad 1.68)
  other vias: 55.5,25.02
N$169  (via drill 0.89 pad 1.68)
  other vias: 55.5,27.56
N$170  (via drill 0.89 pad 1.68)
  other vias: 55.5,30.1
N$171  (via drill 0.89 pad 1.68)
  other vias: 55.5,32.64
N$172  (via drill 0.89 pad 1.68)
  other vias: 55.5,35.18
N$173  (via drill 0.89 pad 1.68)
  other vias: 55.5,37.72
N$174  (via drill 0.89 pad 1.68)
  other vias: 55.5,40.26
N$175  (via drill 0.89 pad 1.68)
  other vias: 55.5,42.8
N$176  (via drill 0.89 pad 1.68)
  other vias: 52.96,42.8
N$177  (via drill 0.89 pad 1.68)
  other vias: 52.96,40.26
N$178  (via drill 0.89 pad 1.68)
  other vias: 52.96,37.72
N$179  (via drill 0.89 pad 1.68)
  other vias: 52.96,35.18
N$180  (via drill 0.89 pad 1.68)
  other vias: 52.96,30.1
N$181  (via drill 0.89 pad 1.68)
  other vias: 52.96,32.64
N$182  (via drill 0.89 pad 1.68)
  other vias: 52.96,27.56
N$183  (via drill 0.89 pad 1.68)
  other vias: 52.96,25.02
N$184  (via drill 0.89 pad 1.68)
  other vias: 52.96,22.48
N$185  (via drill 0.89 pad 1.68)
  other vias: 52.96,19.94
N$186  (via drill 0.89 pad 1.68)
  other vias: 50.42,22.48
N$187  (via drill 0.89 pad 1.68)
  other vias: 50.42,25.02
N$188  (via drill 0.89 pad 1.68)
  other vias: 50.42,27.56
N$189  (via drill 0.89 pad 1.68)
  other vias: 50.42,30.1
N$190  (via drill 0.89 pad 1.68)
  other vias: 50.42,32.64
N$191  (via drill 0.89 pad 1.68)
  other vias: 50.42,35.18
N$192  (via drill 0.89 pad 1.68)
  other vias: 50.42,37.72
N$193  (via drill 0.89 pad 1.68)
  other vias: 50.42,40.26
N$194  (via drill 0.89 pad 1.68)
  other vias: 50.42,42.8
N$195  (via drill 0.89 pad 1.68)
  other vias: 47.88,42.8
N$196  (via drill 0.89 pad 1.68)
  other vias: 47.88,40.26
N$197  (via drill 0.89 pad 1.68)
  other vias: 47.88,37.72
N$198  (via drill 0.89 pad 1.68)
  other vias: 47.88,35.18
N$199  (via drill 0.89 pad 1.68)
  other vias: 47.88,32.64
N$200  (via drill 0.89 pad 1.68)
  other vias: 47.88,30.1
N$201  (via drill 0.89 pad 1.68)
  other vias: 47.88,25.02
N$202  (via drill 0.89 pad 1.68)
  other vias: 47.88,27.56
N$203  (via drill 0.89 pad 1.68)
  other vias: 45.34,27.56
N$204  (via drill 0.89 pad 1.68)
  other vias: 45.34,30.1
N$205  (via drill 0.89 pad 1.68)
  other vias: 45.34,32.64
N$206  (via drill 0.89 pad 1.68)
  other vias: 45.34,35.18
N$207  (via drill 0.89 pad 1.68)
  other vias: 45.34,37.72
N$208  (via drill 0.89 pad 1.68)
  other vias: 45.34,40.26
N$209  (via drill 0.89 pad 1.68)
  other vias: 45.34,42.8
N$210  (via drill 0.89 pad 1.68)
  other vias: 42.8,40.26
N$211  (via drill 0.89 pad 1.68)
  other vias: 42.8,37.72
N$212  (via drill 0.89 pad 1.68)
  other vias: 42.8,35.18
N$213  (via drill 0.89 pad 1.68)
  other vias: 42.8,32.64
N$214  (via drill 0.89 pad 1.68)
  other vias: 42.8,30.1
N$215  (via drill 0.89 pad 1.68)
  other vias: 40.26,32.64
N$216  (via drill 0.89 pad 1.68)
  other vias: 40.26,35.18
N$217  (via drill 0.89 pad 1.68)
  other vias: 40.26,37.72
N$218
  Bottom 0.813: PC.4 PC1.4
N$219  (via drill 0.89 pad 1.68)
  other vias: 83.44,32.64
N$220  (via drill 0.89 pad 1.68)
  other vias: 83.44,35.18
N$221  (via drill 0.89 pad 1.68)
  other vias: 83.44,37.72
N$222  (via drill 0.89 pad 1.68)
  other vias: 85.98,37.72
N$223  (via drill 0.89 pad 1.68)
  other vias: 85.98,35.18
N$224  (via drill 0.89 pad 1.68)
  other vias: 85.98,32.64
N$225  (via drill 0.89 pad 1.65)
  other vias: 42.8,27.56
N$226  (via drill 0.89 pad 1.65)
  other vias: 42.8,25.02
N$227  (via drill 0.89 pad 1.65)
  other vias: 42.8,22.48
N$228
  Bottom 0.813: PC.5 PC1.5
N$229  (via drill 0.89 pad 1.65)
  other vias: 40.26,22.48
N$230  (via drill 0.89 pad 1.65)
  other vias: 40.26,25.02
N$231  (via drill 0.89 pad 1.65)
  other vias: 40.26,27.56
N$232  (via drill 0.89 pad 1.65)
  other vias: 40.26,30.1
N$233
  Bottom 0.813: PC.6 PC1.6
N$234
  Bottom 0.813: POWER.1 POWER1.1
N$236
  Bottom 0.813: POWER.5 POWER1.5
RESET
  Top 0.254: POWER.6 RESET.P$1 48.51,10.41 Q1.3 48.51,15.11 47.12,16.51 42.93,16.51 R15.1
  Bottom 0.813: POWER.6 POWER1.6
RXD
  Top 0.406: PD.1 82.17,56.77 82.17,51.69 82.8,51.05 JP.COM1
  Bottom 0.813: PD.1 PD1.1
TXD
  Top 0.406: PD.2 79.63,56.77 79.63,51.69 78.99,51.05 JP.COM2
  Bottom 0.813: PD.2 PD1.2
VDD5V  (via drill 0.38 pad 1.02)
  Top 0.305: R11.2 47.24,17.4 50.67,13.97 56.39,13.97 POWER1.4
  Top 0.813: U1.3 21.59,28.32 C1.+ v29.08,28.32
  Bottom 0.813: v29.08,28.32 36.7,28.32 38.23,26.8 38.23,12.45 38.23,11.81 41.91,8.13 56.39,8.13 POWER.4 POWER1.4

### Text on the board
tPlace: AREF | GND | 9 | 8 | 7 | 6 | 5 | 4 | 3 | 2 | 13 | 12 | 11 | 10 | Atmega | USB | 13 | 12 | 11 | 10 | 9 | 8 | 7 | 6 | 5 | 4 | 3 | 2 | RX | TX | BEE2 | Bees Shield | V2.12 06/08/2010 | by Albert.Miao | www.seeedstudio.com | RST | 5V | GND | 0 | 1 | 2 | 3 | 4 | 5
bPlace: DIO0 | 3V3 | DIO1 | TX | AD2/DIO2 | RX | AD3/DIO3 | DO8 | AD6/DIO6/!RTS | RESET | 9 | 8 | 7 | 6 | 5 | 4 | 3 | 2 | 1 | 0 | AD5/DIO5 | 13 | 12 | 11 | 10 | RSSI | TX | RX | VREF | PIN7 | ON/SLEEP | PIN8 | DTR | DIO7/CTS | AD4/DIO4 | GND | GND | AD4/DIO4 | DTR | DIO7/CTS | PIN8 | ON/SLEEP | PIN7 | VREF | RSSI | AD5/DIO5 | AD6/DIO6 | RESET | DO8 | AD3/DIO3 | AD2/DIO2 | RX | TX | DIO1 | DIO0 | 3V3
